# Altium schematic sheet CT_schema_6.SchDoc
size 293 x 258 mm
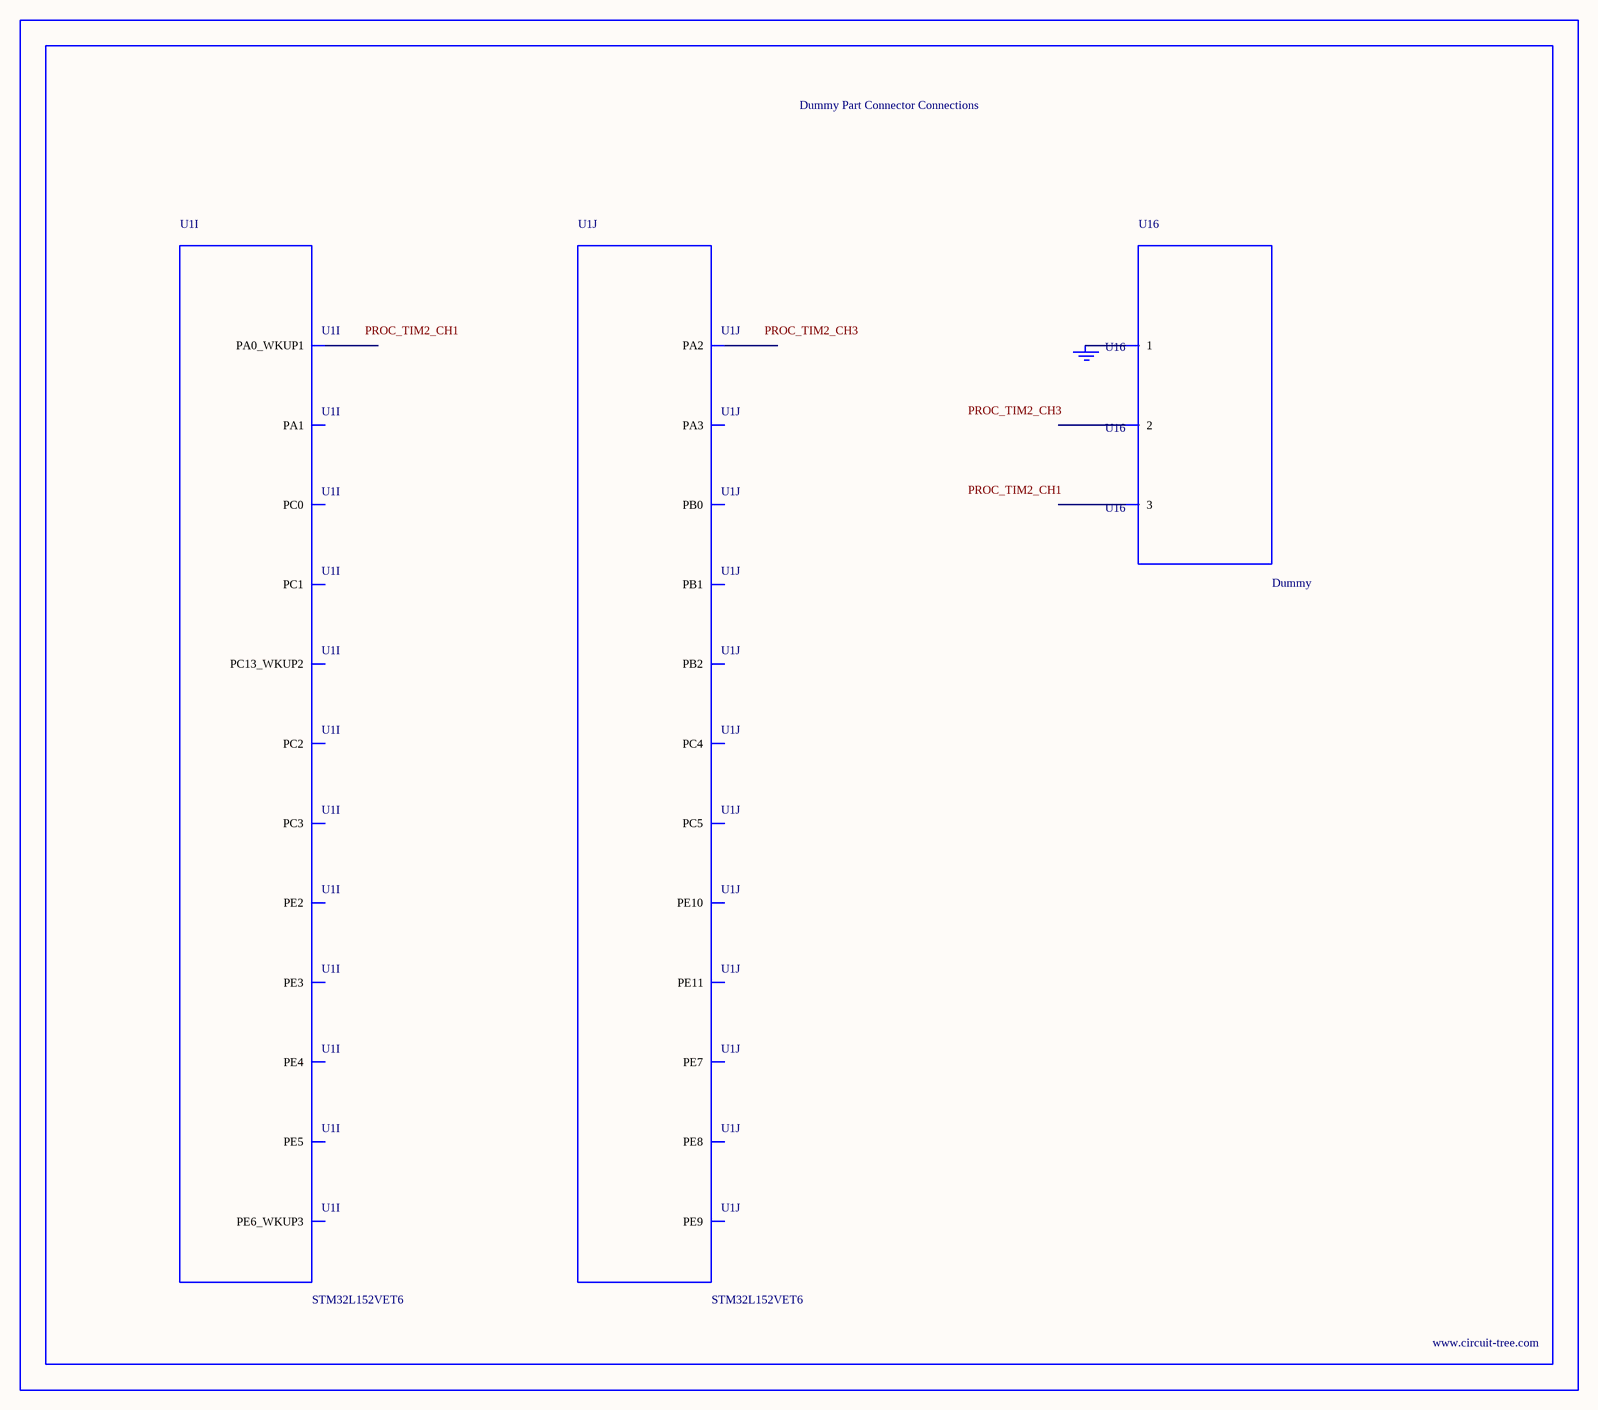
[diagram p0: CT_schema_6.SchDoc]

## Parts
BORDER5  (no value)
GND_INSTANCE_5_0  (no value)
U1  STM32L152VET6  [LQFP100]  (parts I,J of 10)
U16  Dummy  [DUMMY_PACKAGE_146]

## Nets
NetGND_INSTANCE_5_0_0: GND_INSTANCE_5_0.0(GND) U16.1

Not connected (* = marked no-connect by the designer): U1 1(PE2) 2(PE3) 3(PE4) 4(PE5) 5(PE6_WKUP3) 7(PC13_WKUP2) 15(PC0) 16(PC1) 17(PC2) 18(PC3) 23(PA0_WKUP1) 24(PA1) 25(PA2) 26(PA3) 33(PC4) 34(PC5) 35(PB0) 36(PB1) 37(PB2) 38(PE7) 39(PE8) 40(PE9) 41(PE10) 42(PE11); U16 2 3

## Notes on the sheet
- Labels drawn without touching a wire or pin: PROC_TIM2_CH1, PROC_TIM2_CH3

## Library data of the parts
BORDER5 = BORDER_PAGE5
GND_INSTANCE_5_0 = GND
